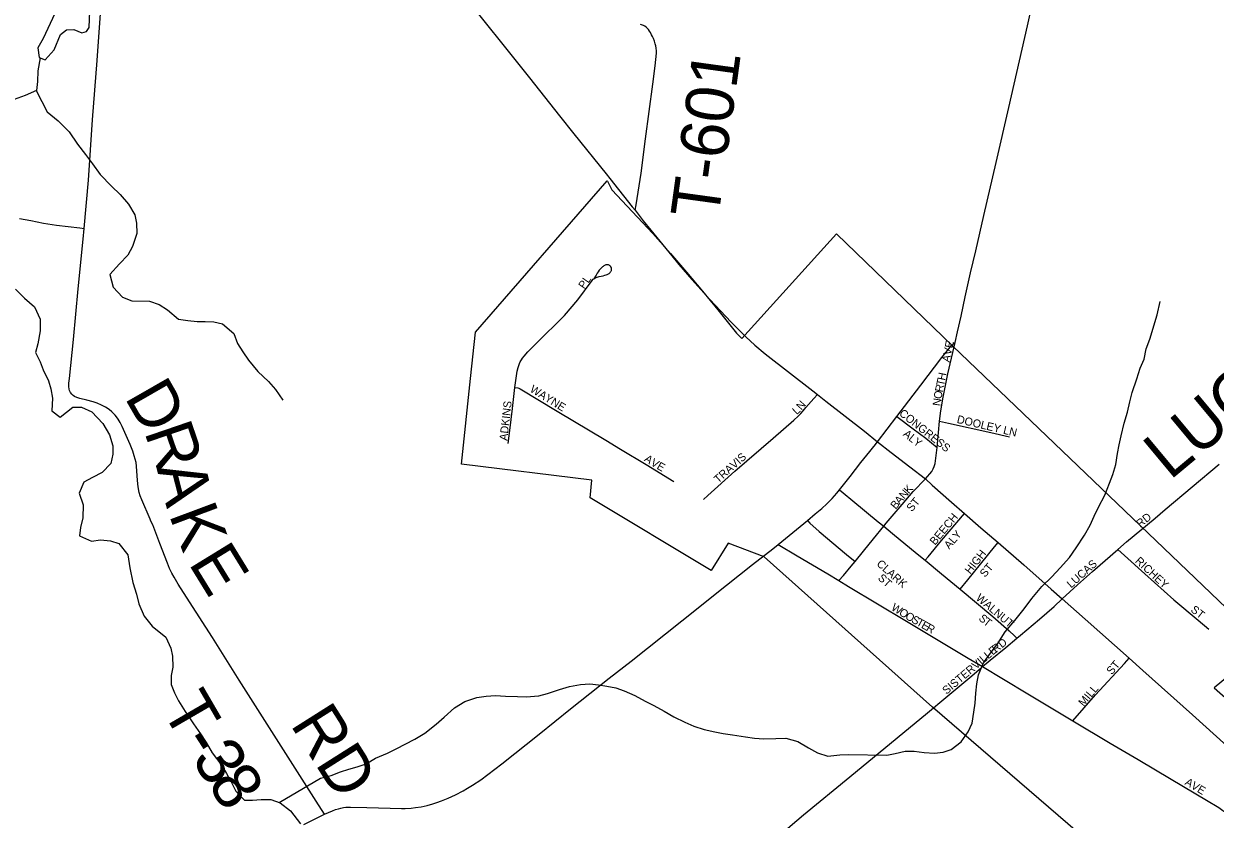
# Model space of a CAD drawing. Extents: x 1451455 to 1749751, y 218250 to 574981.
# Drawn here: x 1539967 to 1547410, y 336504 to 341475 of the extents above; entities that cross this region are included whole.
import ezdxf

# ---------------------------------------------------------------- set-up
doc = ezdxf.new("R2010")
doc.units = 0
for name, color, linetype in [('GM_X_City_Street', 7, 'Continuous'), ('GM_X_City_Street_Text', 7, 'Continuous'), ('GM_X_Corporation', 7, 'Continuous'), ('GM_X_County_Road', 7, 'Continuous'), ('GM_X_County_Road_Text', 7, 'Continuous'), ('GM_X_Minor_Lake', 7, 'Continuous'), ('GM_X_Minor_River', 7, 'Continuous'), ('GM_X_State_Route', 7, 'Continuous'), ('GM_X_Township_Road', 7, 'Continuous'), ('GM_X_Township_Road_Text', 7, 'Continuous')]:
    doc.layers.add(name, color=color, linetype=linetype)

msp = doc.modelspace()

# ---------------------------------------------------------------- linework, layer by layer
at = {"layer": 'GM_X_City_Street'}
for points in [[(1543034.4, 339202.2), (1543048.6, 339304.7), (1543054.4, 339327.5), (1543058.7, 339340.5), (1543063.5, 339353.1), (1543068.7, 339363.4), (1543075.7, 339375.2), (1543082.2, 339384.8), (1543092.6, 339398.6), (1543116.8, 339425.3), (1543167.5, 339476.7), (1543343.9, 339652.3), (1543427.7, 339749), (1543518.3, 339871.1), (1543524.5, 339878.1), (1543528.6, 339882.1), (1543536.8, 339887.3), (1543548.9, 339892.3), (1543561, 339895.6), (1543574.4, 339898.3), (1543586.3, 339900.9), (1543596.7, 339903.4), (1543605, 339906.1), (1543612.2, 339909), (1543623.8, 339915.5), (1543628, 339918.7), (1543630.8, 339921.5), (1543633, 339924.3), (1543634.9, 339927.3), (1543636.4, 339930.2), (1543637.7, 339933.2), (1543638.4, 339936.2), (1543638.9, 339939.5), (1543639.1, 339942.8), (1543638.6, 339945.9), (1543637.8, 339949.3), (1543636.7, 339952.1), (1543635.3, 339955), (1543633.4, 339957.8), (1543631.2, 339960.4), (1543629, 339962.6), (1543626.4, 339964.4), (1543623.5, 339966.4), (1543619.6, 339967.9), (1543615.2, 339969), (1543611.2, 339969.2), (1543607, 339969), (1543603, 339968.2), (1543599.3, 339966.8), (1543595.4, 339965.1), (1543589.8, 339961.9), (1543585.8, 339959.2), (1543581.8, 339956.2), (1543573.9, 339948.6), (1543568, 339941.9), (1543561.8, 339934.3), (1543555.1, 339925), (1543549.2, 339916), (1543541.8, 339904.3), (1543528.6, 339882.1)], [(1545687.5, 338991.3), (1545695.9, 339055.4), (1545711.4, 339142.7), (1545740.3, 339287.4), (1545785.3, 339482.6)], [(1542992.2, 338852.5), (1543002.4, 338933.8), (1543019.3, 339070.5), (1543034.4, 339202.2)], [(1543034.4, 339202.2), (1543052.6, 339200.2), (1543059.9, 339198), (1543066.9, 339194.1), (1543298.1, 339053.4), (1543602.2, 338872.7), (1543694.8, 338817.1), (1543854.4, 338720.2), (1544027.9, 338614.8)], [(1544213.9, 338503.1), (1544241.1, 338528), (1544409.2, 338680.2), (1544648.6, 338885.8), (1544776.9, 338998.1), (1544804.9, 339023.9), (1544822.1, 339039.7), (1544836, 339056.1), (1544852.5, 339077), (1544902.1, 339134.1), (1544924.5, 339157.7)], [(1545420.4, 339021.9), (1545523.3, 338943.8), (1545602, 338885.4), (1545672.9, 338827.3)], [(1545672.9, 338827.3), (1545681.2, 338920.7), (1545687.5, 338991.3)], [(1545687.5, 338991.3), (1545744.7, 338979.1), (1546007.3, 338921), (1546125.3, 338894.3)], [(1545600.6, 338631.2), (1545638.8, 338676.4), (1545647.9, 338694), (1545654.8, 338708.8), (1545660, 338727.9), (1545669.2, 338794.5), (1545672.9, 338827.3)], [(1545339.7, 338335.2), (1545355.4, 338354.5), (1545455, 338471.7), (1545522.9, 338551.2), (1545600.6, 338631.2)], [(1545063.7, 338563), (1545086.2, 338544), (1545145.7, 338493.9), (1545304.9, 338363.6), (1545339.7, 338335.2)], [(1546801.3, 338190.7), (1546856.8, 338237.2), (1547034, 338385.7), (1547097.1, 338439.5)], [(1544862.5, 338370.6), (1544878.2, 338355.2), (1544936.8, 338302.7), (1545106.6, 338158.1), (1545161, 338115.3)], [(1545598, 338122.3), (1545616.2, 338144.5), (1545699.9, 338246.3), (1545795.8, 338359.4), (1545844, 338415.3)], [(1545161, 338115.3), (1545213.8, 338178.8), (1545274.9, 338255.7), (1545339.7, 338335.2)], [(1545339.7, 338335.2), (1545394.6, 338289.9), (1545548.4, 338163.3), (1545598, 338122.3)], [(1544680.4, 338221.3), (1544798.6, 338150.3), (1544990.8, 338037.2), (1545059.5, 337996)], [(1545817.7, 337942), (1545865.5, 338000.3), (1546031.9, 338206.7), (1546053.6, 338233.5)], [(1546454.1, 337881.3), (1546548.8, 337969.8), (1546642.5, 338052.2), (1546801.3, 338190.7)], [(1546801.3, 338190.7), (1546843.1, 338153), (1546970.4, 338038.2), (1547151.6, 337874.7), (1547302.6, 337748), (1547369.8, 337691.7)], [(1545059.5, 337996), (1545087.7, 338028), (1545136, 338085.5), (1545161, 338115.3)], [(1545598, 338122.3), (1545699.7, 338038.1), (1545817.7, 337942)], [(1545059.5, 337996), (1545120.1, 337959.5), (1545482.1, 337741), (1545721.7, 337598.5), (1545867.7, 337510.6), (1545956.8, 337458.9)], [(1545817.7, 337942), (1546021.7, 337770.2), (1546123.3, 337682), (1546156.2, 337649.6), (1546170.5, 337635.5)], [(1546170.5, 337635.5), (1546194.4, 337655.1), (1546311.4, 337755.3), (1546403.8, 337834.3), (1546454.1, 337881.3)], [(1545956.8, 337458.9), (1546004.6, 337499), (1546101.2, 337577.7), (1546170.5, 337635.5)], [(1545727.2, 337264.8), (1545890, 337401.1), (1545949.4, 337452.7), (1545956.8, 337458.9)], [(1545956.8, 337458.9), (1546086.8, 337379.1), (1546240.3, 337287), (1546415.9, 337181.6), (1546520, 337118.4)], [(1546520, 337118.4), (1546662, 337281.2), (1546843.2, 337478.2), (1546872.3, 337510.7)], [(1546520, 337118.4), (1546753.5, 336979.3), (1546929.1, 336876.7), (1547135, 336754.6), (1547354.7, 336624), (1547432, 336577.7), (1547457, 336559.4), (1547494.2, 336534.4)]]:
    msp.add_lwpolyline(points, dxfattribs=at)
at = {"layer": 'GM_X_Corporation'}
msp.add_lwpolyline([(1547681.9, 335445.7), (1545643.8, 337204.7), (1544591.6, 338143), (1544367.5, 338229), (1544261.5, 338059.3), (1543505.5, 338513.6), (1543515.1, 338623.2), (1542701.2, 338723.1), (1542757.5, 339258.1), (1542787.9, 339547.5), (1543610.9, 340494), (1543612.6, 340491.8), (1543641.5, 340437.1), (1543896.4, 340163.5), (1544008.1, 340039), (1544107.9, 339922.8), (1544207.7, 339804.6), (1544303.5, 339688.4), (1544418.8, 339541.8), (1544452.7, 339508.8), (1545044.4, 340162), (1545771, 339460.5), (1547724.6, 337589.6), (1547404.3, 337324.3), (1548995.5, 335923.4)], dxfattribs=at)
at = {"layer": 'GM_X_County_Road'}
msp.add_lwpolyline([(1547097.1, 338439.5), (1547435, 338723.6)], dxfattribs=at)
at = {"layer": 'GM_X_Minor_Lake'}
msp.add_lwpolyline([(1540174, 342071.1), (1540199.4, 342038.6), (1540215, 342012.3), (1540205, 341898.2), (1540217.2, 341793.7), (1540231.5, 341693.2), (1540087.7, 341382.8), (1540054.7, 341325.2), (1540063.6, 341264.9), (1540099.4, 341250.3), (1540156.6, 341311.5), (1540196.4, 341409), (1540233, 341436.5), (1540279.1, 341439.7), (1540328.8, 341418.8), (1540359, 341426.3), (1540375.5, 341452.1), (1540403.3, 342121.3)], dxfattribs=at)
at = {"layer": 'GM_X_Minor_River'}
for points in [[(1540068.2, 341263.1), (1540054.1, 341180.9), (1540053, 341114.7), (1540046, 341058.7), (1539975.3, 341027.8), (1539906.7, 341002.9)], [(1540044.2, 341057.9), (1540078.8, 340989.9), (1540113.8, 340925.2), (1540180.9, 340867.8), (1540249.9, 340800.5), (1540302.6, 340723.4), (1540351.6, 340658.3), (1540396.7, 340599.4), (1540443.6, 340532.4), (1540514.5, 340461), (1540569.7, 340407.9), (1540620.7, 340346.8), (1540659.6, 340282), (1540670.7, 340229.6), (1540673.6, 340165.4), (1540646.1, 340083.6), (1540617.1, 340030), (1540564.1, 339974.8), (1540504.8, 339907.6), (1540525.5, 339829), (1540584.5, 339765.8), (1540642.2, 339742.7), (1540752.4, 339740.8), (1540812.1, 339721.8), (1540865.6, 339686.7), (1540932.8, 339629.4), (1540992.7, 339620.4), (1541050.8, 339615.3), (1541100.8, 339614.5), (1541154.9, 339613.5), (1541208.8, 339600.6), (1541279.9, 339539.2), (1541302.8, 339476.6), (1541336, 339425.9), (1541371.2, 339373.1), (1541428, 339301.9), (1541495.1, 339240.6), (1541540.3, 339189.7), (1541585.2, 339122.7)], [(1539916, 339817.4), (1539971.1, 339760.3), (1540034.3, 339707.1), (1540069, 339628.2), (1540069.8, 339556), (1540054.3, 339476), (1540039.3, 339420.1), (1540068.4, 339363.5), (1540087.6, 339313), (1540120.4, 339244.2), (1540135.6, 339193.8), (1540146.6, 339135.4), (1540141.2, 339055.3), (1540194.6, 339016.3), (1540273.9, 339079.1), (1540328, 339080.2), (1540391.6, 339051), (1540460.4, 338977.6), (1540501.3, 338906.7), (1540522.1, 338838.1), (1540523.2, 338785.9), (1540510.2, 338728), (1540457.1, 338670.7), (1540396.4, 338639.6), (1540341.8, 338610.5), (1540312.5, 338540.8), (1540337.3, 338468.1), (1540335.9, 338387.9), (1540320.8, 338328), (1540313.9, 338275.9), (1540389.5, 338242.5), (1540445.7, 338249.6), (1540507.8, 338244.5), (1540561.6, 338227.5), (1540616.4, 338156.4), (1540629.1, 338075.9), (1540647.5, 337983.3), (1540670.3, 337910.7), (1540685.2, 337850.2), (1540718, 337773.4), (1540769, 337710.4), (1540854, 337642.7), (1540884.8, 337573.9), (1540896, 337523.6), (1540898.8, 337455.3), (1540887.9, 337403.3), (1540886.8, 337345.2), (1540908, 337294.7), (1540933.2, 337244.1), (1540974.1, 337177.1), (1541026.8, 337100), (1541071.8, 337037), (1541107, 336984.2), (1541143.9, 336919.4), (1541196.8, 336848.3), (1541233.8, 336789.5), (1541263, 336736.8), (1541292.1, 336680.1), (1541345.2, 336623), (1541395.3, 336624.1), (1541449.5, 336627.2), (1541509.6, 336628.2), (1541569.3, 336607.1), (1541632.6, 336555.8), (1541695.3, 336474.5)], [(1546965.5, 339379.6), (1546978.5, 339443.5), (1547001.5, 339503.2), (1547048, 339656.7), (1547065.3, 339738.5)], [(1541562.5, 336609.5), (1541821, 336759.7), (1541887.3, 336776.7), (1541945.7, 336799.8), (1541998.1, 336817), (1542050.3, 336832.2), (1542106.7, 336851.3), (1542163.3, 336886.5), (1542239.9, 336917.3), (1542296.4, 336946.4), (1542348.9, 336973.6), (1542409.4, 337004.7), (1542472.1, 337041.8), (1542543, 337098.8), (1542593.8, 337142), (1542656.8, 337201.1), (1542721.5, 337240.1), (1542797.9, 337265), (1542856.1, 337274), (1542914.2, 337277.1), (1542976.2, 337274.1), (1543050.2, 337270.9), (1543106.3, 337270), (1543184.4, 337274.8), (1543238.7, 337289.9), (1543313.1, 337314.8), (1543375.5, 337333.8), (1543443.8, 337346.7), (1543503.9, 337349.8), (1543557.8, 337344.9), (1543609.7, 337336), (1543665.6, 337325.1), (1543717.3, 337306.3), (1543784.9, 337277.1), (1543848.4, 337242), (1543902, 337215.1), (1543967.5, 337180), (1544027, 337145), (1544096.5, 337109.8), (1544152.1, 337084.9), (1544217.9, 337065.8), (1544283.7, 337050.7), (1544335.5, 337039.9), (1544395.4, 337030.9), (1544475.3, 337019.6), (1544531.2, 337010.7), (1544589.2, 337005.7), (1544665.3, 337008.5), (1544727.4, 337011.5), (1544803.1, 336990.3), (1544868.5, 336951.1), (1544926.1, 336918.2), (1544989.8, 336899.1), (1545064, 336905.9), (1545118.1, 336909.1), (1545358.2, 336905.2), (1545410.4, 336914.4), (1545472.7, 336929.4), (1545528.7, 336928.5), (1545592.7, 336921.5), (1545656.6, 336916.4), (1545710.8, 336923.6), (1545761.1, 336940.8), (1545823.9, 336987.9), (1545867, 337051.3), (1545891.9, 337105), (1545903, 337172.9), (1545909.9, 337228.9), (1545914.9, 337290.9), (1545921.8, 337350.9), (1545930.8, 337406.9), (1545962, 337480.5), (1546013.1, 337549.8), (1546052, 337603.3), (1546097.2, 337674.7), (1546158.4, 337745.8), (1546217.6, 337819), (1546264.7, 337884.4), (1546326, 337959.5), (1546389, 338018.6), (1546442, 338075.8), (1546499, 338139), (1546542.1, 338200.4), (1546593.4, 338279.8), (1546628.4, 338341.3), (1546653.3, 338397), (1546680.3, 338454.6), (1546719.5, 338530.1), (1546750.7, 338603.8), (1546769.6, 338657.5), (1546788.7, 338721.3), (1546799.8, 338789.3), (1546810.7, 338843.2), (1546823.6, 338899.1), (1546840.9, 338978.9), (1546862, 339048.7), (1546877.1, 339112.6), (1546892, 339170.4), (1546921.4, 339256.1), (1546940.5, 339323.9), (1546965.5, 339379.6)]]:
    msp.add_lwpolyline(points, dxfattribs=at)
at = {"layer": 'GM_X_State_Route'}
for points in [[(1545965, 340276.6), (1545965, 340276.6), (1546041, 340609.1), (1546120.3, 340951), (1546237.3, 341462.7), (1546342.5, 341933.3), (1546476.2, 342515.2), (1546576, 342953.4), (1546614.5, 343112.5), (1546621.3, 343135.7), (1546628.3, 343156), (1546642.6, 343192.4), (1546657.9, 343224.7), (1546673.5, 343253), (1546689.2, 343277.4), (1546700.7, 343294.3), (1546709.8, 343306.4), (1546749.5, 343358.9), (1546884.5, 343535.3), (1546992.4, 343682.9), (1547095.6, 343824), (1547169.7, 343924.1), (1547346.4, 344160.7), (1547637.1, 344549.5)], [(1542798.7, 341545.9), (1542875.2, 341451.7), (1542934, 341377), (1543127.2, 341136.7), (1543313.6, 340900.2), (1543402.6, 340786.8), (1543606.2, 340537.1), (1543627.3, 340509)], [(1543627.3, 340509), (1543768.4, 340331.6), (1543785.7, 340309.5), (1543837, 340243.5), (1543884.6, 340184.7), (1544014.8, 340024), (1544058.9, 339970.9), (1544141.1, 339876.8), (1544253.8, 339752.9), (1544386.2, 339611.2), (1544478.1, 339518.5)], [(1545801, 339550), (1545822.6, 339647.3), (1545847.6, 339768.8), (1545880.6, 339919.1), (1545913.9, 340056.1), (1545965, 340276.6)], [(1545276.8, 338833.8), (1545278.9, 338836.4), (1545299.9, 338862.9), (1545360.3, 338942.7), (1545420.4, 339021.9), (1545570.1, 339217.6), (1545701.9, 339389), (1545762, 339464.1), (1545769.9, 339471.4), (1545776.6, 339476.3), (1545785.3, 339482.6), (1545801, 339550)], [(1544478.1, 339518.5), (1544534.8, 339466.3), (1544598.2, 339413.3), (1544895.8, 339180.6), (1544924.5, 339157.7), (1544977.2, 339116.6), (1545218.2, 338928.6), (1545299.9, 338862.9)], [(1544680.4, 338221.3), (1544862.5, 338370.6), (1544911.5, 338411.8), (1544952.2, 338446.1), (1544983.3, 338474.6), (1545017.6, 338509.3), (1545045.6, 338541.1), (1545063.7, 338563), (1545128.6, 338646.3), (1545196.9, 338734.4), (1545252.7, 338803), (1545276.8, 338833.8)], [(1545299.9, 338862.9), (1545385.9, 338795.6), (1545502.8, 338706), (1545600.6, 338631.2), (1545642, 338591.5), (1545763.4, 338485), (1545844, 338415.3), (1545946.9, 338326.1), (1546053.6, 338233.5), (1546214.1, 338093.5), (1546385, 337942.4), (1546454.1, 337881.3), (1546597.6, 337754.9), (1546781.7, 337591.6), (1546872.2, 337510.8), (1546872.3, 337510.7), (1546957.9, 337434.5), (1547268.7, 337157.2), (1547482.2, 336963.1), (1547704.6, 336760.6), (1547712.4, 336753.5)], [(1544645.9, 338194.5), (1544680.4, 338221.3)], [(1541717.2, 336471.1), (1541845.5, 336535.8), (1541894.8, 336557.3), (1541914.4, 336563.9), (1541932.1, 336569.4), (1541948.5, 336573.6), (1541963.8, 336576.7), (1541979.6, 336578.5), (1542008.5, 336579.6), (1542110.4, 336578), (1542254.7, 336572.6), (1542325.9, 336571.2), (1542350.3, 336571.2), (1542386.3, 336573.6), (1542413.7, 336576.7), (1542449.1, 336582.2), (1542486.9, 336590.1), (1542521.6, 336600.5), (1542547.8, 336609), (1542575.9, 336618.8), (1542617.3, 336635.7), (1542664.9, 336657.4), (1542711.1, 336681.6), (1542739.9, 336697.7), (1542769.1, 336716), (1542821.7, 336751.3), (1542952.9, 336849.3), (1543185.9, 337035.9), (1543383, 337193.7), (1543624.2, 337386), (1543761.3, 337492.9), (1544077.1, 337744.1), (1544357, 337966.6), (1544518.5, 338095.5), (1544645.9, 338194.5)]]:
    msp.add_lwpolyline(points, dxfattribs=at)
at = {"layer": 'GM_X_Township_Road'}
for points in [[(1540344.3, 340196.2), (1540371.1, 340498.1), (1540395.8, 340874.2), (1540425.5, 341245.9), (1540469.9, 341863.6), (1540515.6, 342417.9), (1540563.9, 342992.3), (1540600.1, 343436.7), (1540603.8, 343482.2)], [(1543785.7, 340309.5), (1543791.8, 340344.6), (1543824.4, 340542), (1543851, 340756.9), (1543897.5, 341098.3), (1543910.9, 341212.3), (1543919.8, 341290.5), (1543919.8, 341306.8), (1543917.7, 341323), (1543915, 341337.2), (1543912.1, 341350.5), (1543907.3, 341366.5), (1543900.7, 341382.2), (1543894.5, 341395.8), (1543889.2, 341405.9), (1543881.2, 341420.2), (1543876.4, 341428.7), (1543869.5, 341438.6), (1543863.8, 341445.1), (1543854.7, 341454.5), (1543846.8, 341460.4), (1543838.2, 341465), (1543831.7, 341467.3), (1543825.7, 341469.1), (1543819.3, 341470.2)], [(1539939.4, 340259.2), (1540010.1, 340245.1), (1540090.7, 340230), (1540171.6, 340217.4), (1540317.9, 340199.5), (1540344.3, 340196.2)], [(1541845.5, 336535.8), (1541793.7, 336616.6), (1541559.9, 336982.8), (1541312.3, 337373.4), (1541144.9, 337640), (1541001.8, 337863.6), (1540930.9, 337974), (1540905.6, 338016.1), (1540891.7, 338042.2), (1540877.6, 338071.7), (1540863.9, 338105.1), (1540817.6, 338227.8), (1540772, 338343.8), (1540761, 338367.7), (1540755.9, 338379.8), (1540703.3, 338500.6), (1540694.1, 338525.6), (1540688, 338545.7), (1540683, 338568.8), (1540679.5, 338598.1), (1540675.1, 338650.4), (1540670.9, 338710.3), (1540667.9, 338734.1), (1540663, 338754.8), (1540656.3, 338776.1), (1540647.2, 338804.8), (1540631.9, 338845), (1540580.7, 338957.8), (1540568.5, 338982.8), (1540555.7, 339004.1), (1540545.2, 339017.8), (1540537.4, 339028.2), (1540528.6, 339037.8), (1540517.5, 339049.7), (1540499.5, 339064), (1540477.6, 339078.4), (1540451.6, 339092.3), (1540424.4, 339104), (1540399.6, 339112.4), (1540361.5, 339122.2), (1540316.7, 339132.7), (1540297.8, 339138.7), (1540283.1, 339145.8), (1540275.2, 339151.6), (1540266, 339160.8), (1540258.4, 339171.4), (1540252.8, 339183.1), (1540249.9, 339192.5), (1540247.5, 339208.7), (1540247.5, 339218.8), (1540247.8, 339228.4), (1540251.4, 339257.7), (1540278.2, 339502.2), (1540306.9, 339819), (1540338.4, 340129), (1540344.3, 340196.2)], [(1542655.2, 334698.7), (1542824.4, 334843), (1543015.3, 335003.4), (1543227, 335179.8), (1543483.7, 335394.4), (1543759.5, 335627.2), (1543987.3, 335815.1), (1544248.7, 336034.5), (1544503, 336247), (1544838.9, 336530.6), (1545126.7, 336769.4), (1545423, 337013.5), (1545613.5, 337169.2), (1545727.2, 337264.8)]]:
    msp.add_lwpolyline(points, dxfattribs=at)

# ---------------------------------------------------------------- texts
at = {"layer": 'GM_X_City_Street_Text'}
for s, rotation, p in [('PL', 55.29959, (1543468.2, 339813.8)), ('AVE', 78.31299, (1545750.3, 339357.2)), ('T', 78.02831, (1545715.2, 339208.5)), ('H', 78.02354, (1545722.5, 339243)), ('WAYNE', 328.46517, (1543124.4, 339178.5)), ('O', 79.69319, (1545699.2, 339126.9)), ('R', 78.11134, (1545707, 339169.8)), ('ADKINS', 83.41749, (1542987, 338868)), ('N', 49.22089, (1544825.2, 339057.1)), ('N', 81.7648, (1545693, 339083.8)), ('L', 42.7781, (1544795.2, 339028.8)), ('CONGRESS', 321.58251, (1545431, 339032.6)), ('DOOLEY LN', 346.84162, (1545792.7, 338981.6)), ('A', 320.72059, (1545455.8, 338904.4)), ('L', 321.07052, (1545490.1, 338876.3)), ('Y', 323.64429, (1545519.5, 338852.7)), ('A', 325.49767, (1543839, 338746.1)), ('V', 329.86221, (1543878.8, 338718.9)), ('E', 330.25546, (1543917.1, 338696.6)), ('TRAVIS', 41.81899, (1544305.5, 338601)), ('K', 48.17768, (1545496.3, 338534.1)), ('A', 49.47702, (1545439.3, 338467.5)), ('N', 49.47702, (1545467.9, 338500.9)), ('ST', 50.19174, (1545514.8, 338421.8)), ('B', 49.47772, (1545413.6, 338437.4)), ('BEECH', 50.35635, (1545659.9, 338212.9)), ('RD', 38.65536, (1546941.6, 338324.2)), ('Y', 49.3891, (1545800.8, 338248.7)), ('A', 48.60332, (1545748.2, 338188.5)), ('L', 49.32689, (1545777.8, 338222)), ('HIGH', 51.84346, (1545879.7, 338032.3)), ('RICHEY', 317.29225, (1546905.6, 338112.5)), ('CLARK', 318.46798, (1545290.6, 338094)), ('ST', 49.76552, (1545972, 338012.2)), ('LUCAS', 41.63222, (1546510, 337945.5)), ('ST', 317.48791, (1545298.7, 338006.1)), ('WALNUT', 319.70765, (1545910.9, 337879.6)), ('W', 328.02848, (1545381.7, 337814.5)), ('ST', 322.43182, (1547252.5, 337805.1)), ('O', 328.0252, (1545430.2, 337784.2)), ('O', 329.39637, (1545468.7, 337760.2)), ('S', 330.73277, (1545507.7, 337737.2)), ('T', 330.80566, (1545538.4, 337719.9)), ('S', 318.20877, (1545928.3, 337753.9)), ('T', 322.49639, (1545957.7, 337727.9)), ('E', 330.80076, (1545569.2, 337702.7)), ('R', 330.80034, (1545599.9, 337685.6)), ('RD', 38.65536, (1546039.7, 337541)), ('SISTERVILLE', 40.31377, (1545731.4, 337281.2)), ('ST', 50.19174, (1546764.3, 337403.3)), ('MILL', 49.761, (1546588.3, 337205.4)), ('AVE', 329.03689, (1547216.4, 336723.4))]:
    msp.add_text(s, height=50, rotation=rotation, dxfattribs=at).set_placement(p)
at = {"layer": 'GM_X_County_Road_Text'}
msp.add_text('LUCAS', height=300, rotation=39.80475, dxfattribs=at).set_placement((1547127, 338618.8))
at = {"layer": 'GM_X_Township_Road_Text'}
for s, rotation, p in [('T-601', 82.1534, (1544303.9, 340246.3)), ('D', 299.82667, (1540592.7, 339142)), ('R', 288.92001, (1540717.8, 338926.7)), ('A', 284.19307, (1540795.8, 338699.8)), ('K', 290.49534, (1540871.3, 338409.5)), ('E', 301.58242, (1540991.5, 338105.3)), ('T', 300.16775, (1540823.7, 337192.3)), ('RD', 302.31985, (1541627.7, 337097.6)), ('-', 302.5518, (1540943.5, 336986.7)), ('3', 302.76602, (1541010.5, 336881.8)), ('8', 302.85905, (1541110.8, 336726))]:
    msp.add_text(s, height=300, rotation=rotation, dxfattribs=at).set_placement(p)

doc.saveas('drawing.dxf')
